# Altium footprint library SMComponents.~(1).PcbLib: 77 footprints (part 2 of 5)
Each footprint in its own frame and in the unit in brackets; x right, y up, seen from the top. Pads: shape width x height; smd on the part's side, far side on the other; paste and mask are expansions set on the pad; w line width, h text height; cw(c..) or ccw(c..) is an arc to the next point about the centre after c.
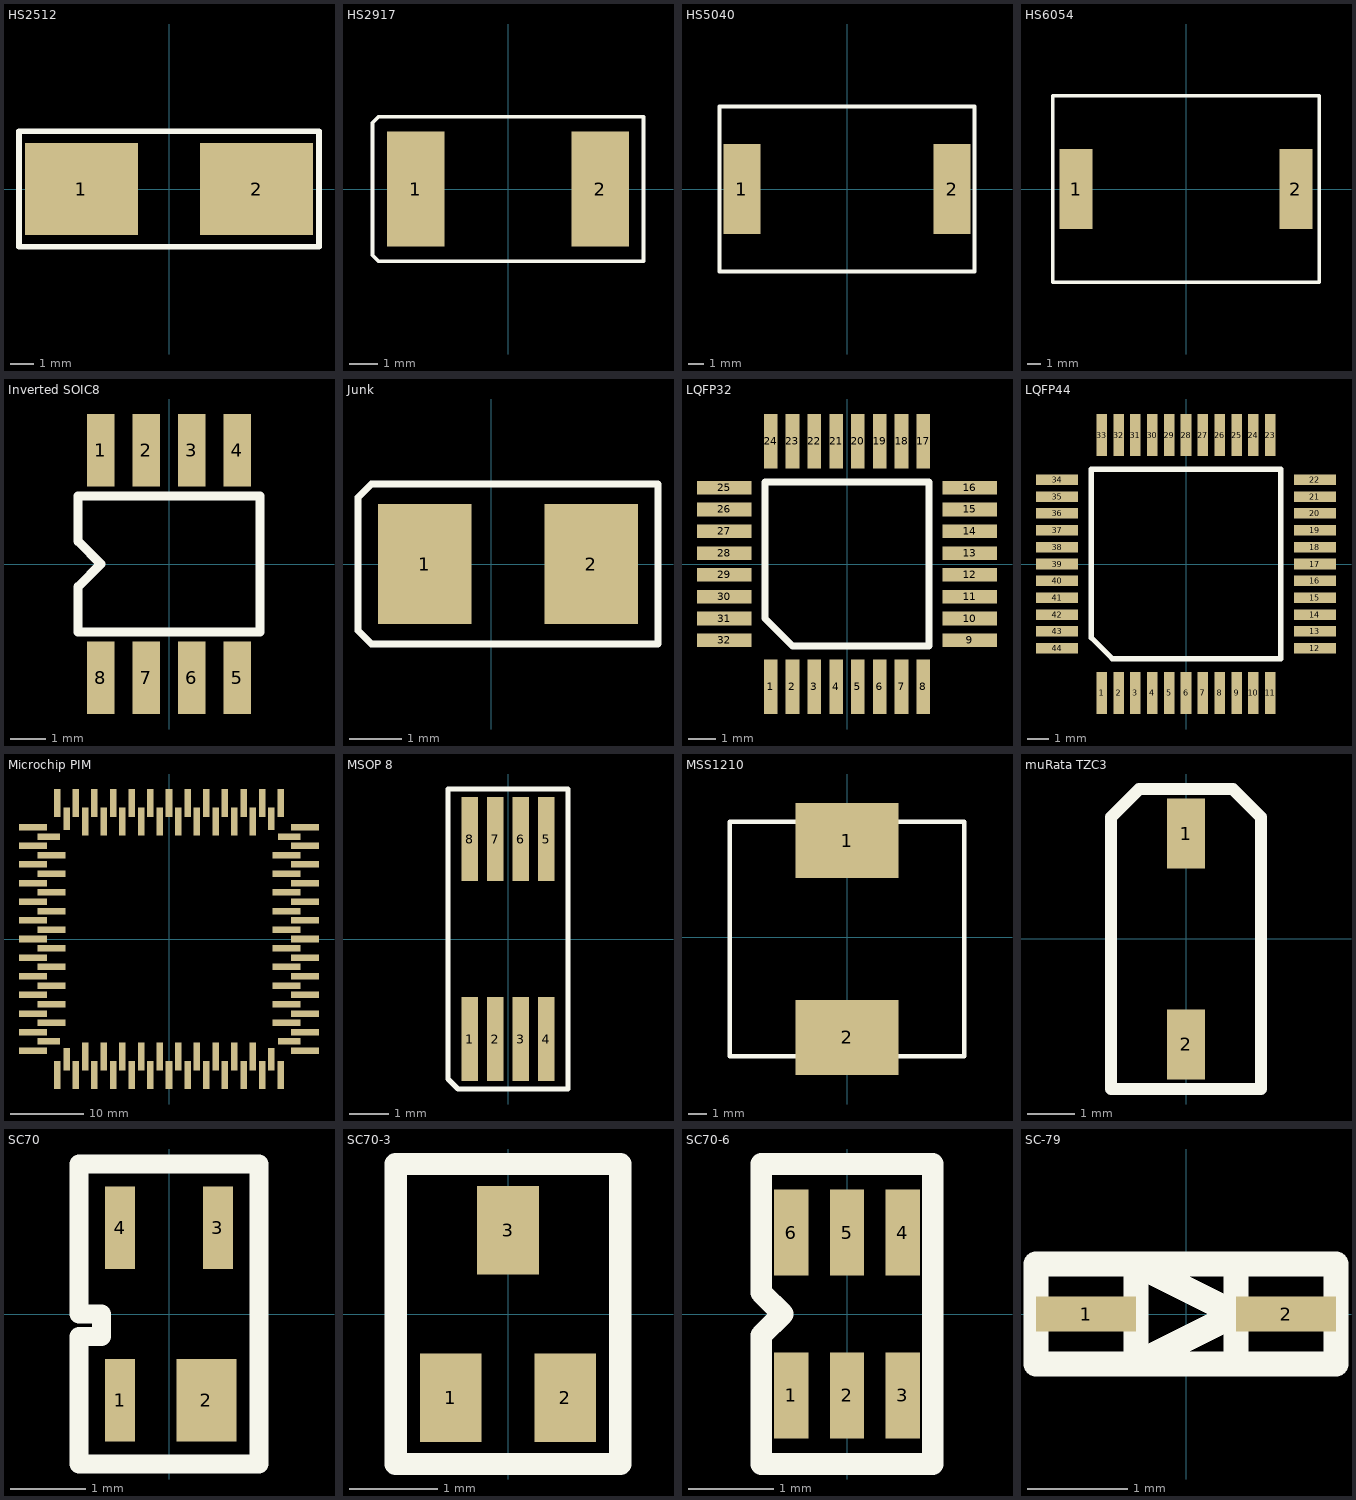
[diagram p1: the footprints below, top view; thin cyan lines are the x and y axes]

## HS2512 [mm] "2512"
height 2.6
pads (2):
  rect 4.9x4 smd: 1(-3.8,0) 2(3.8,0)
Top Overlay:
  lines w0.254: -6.5,-2.5 -6.5,2.5 6.5,2.5 6.5,-2.5 -6.5,-2.5

## HS2917 [mm] "2917 - Tant codes D & E"
height 4.1
pads (2):
  rect 2x4 smd: 1(-3.2,0) 2(3.2,0)
Top Overlay:
  lines w0.127: -4.7,-2.3 -4.7,2.3 -4.5,2.5 4.7,2.5 4.7,-2.5 -4.5,-2.5 -4.7,-2.3

## HS5040 [mm] "5040 SMD such as Wima SMD-PET"
height 6
pads (2):
  rect 2.5x6 smd: 1(-7,0) 2(7,0)
Top Overlay:
  lines w0.254: -8.5,-5.5 -8.5,5.5 8.5,5.5 8.5,-5.5 -8.5,-5.5

## HS6054 [mm] "6054 SMD such as Wima SMD-PET"
height 6
pads (2):
  rect 2.5x6 smd: 1(-8.25,0) 2(8.25,0)
Top Overlay:
  lines w0.254: -10,-7 -10,7 10,7 10,-7 -10,-7

## Inverted SOIC8 [mil] "Inverted to allow access to power pad - cut out in board!"
pads (8):
  rect 30x80 smd: 1(-75,125) 2(-25,125) 3(25,125) 4(75,125) 5(75,-125) 6(25,-125) 7(-25,-125) 8(-75,-125)
Top Overlay:
  lines w10: -100,-75 100,-75 100,75 -100,75 -100,25 -75,0 -100,-25 -100,-75
Bottom Overlay:
  lines w10: -98.43,-78.74 -98.43,78.74 98.43,78.74 98.43,-78.74 -98.43,-78.74

## Junk [mil] "Tant case B (A will also fit!)"
height 74.8
pads (2):
  rect 70x90 smd: 1(-50,0) 2(75,0)
Top Overlay:
  lines w5: -100,-50 -100,50 -90,60 125,60 125,-60 -90,-60 -100,-50

## LQFP32 [mm] "LQFP32"
height 1.6
pads (32):
  rect 0.5x2 smd: 1(-2.8,-4.5) 2(-2,-4.5) 3(-1.2,-4.5) 4(-0.4,-4.5) 5(0.4,-4.5) 6(1.2,-4.5) 7(2,-4.5) 8(2.8,-4.5) 17(2.8,4.5) 18(2,4.5) 19(1.2,4.5) 20(0.4,4.5) 21(-0.4,4.5) 22(-1.2,4.5) 23(-2,4.5) 24(-2.8,4.5)
  rect 2x0.5 smd: 9(4.5,-2.8) 10(4.5,-2) 11(4.5,-1.2) 12(4.5,-0.4) 13(4.5,0.4) 14(4.5,1.2) 15(4.5,2) 16(4.5,2.8) 25(-4.5,2.8) 26(-4.5,2) 27(-4.5,1.2) 28(-4.5,0.4) 29(-4.5,-0.4) 30(-4.5,-1.2) 31(-4.5,-2) 32(-4.5,-2.8)
Top Overlay:
  lines w0.254: -3,-2 -2,-3 3,-3 3,3 -3,3 -3,-2

## LQFP44 [mm] "LQFP44"
height 1.6
pads (44):
  rect 0.5x2 smd: 1(-4,-6.125) 2(-3.2,-6.125) 3(-2.4,-6.125) 4(-1.6,-6.125) 5(-0.8,-6.125) 6(0,-6.125) 7(0.8,-6.125) 8(1.6,-6.125) 9(2.4,-6.125) 10(3.2,-6.125) 11(4,-6.125) 23(4,6.125) 24(3.2,6.125) 25(2.4,6.125) 26(1.6,6.125) 27(0.8,6.125) 28(0,6.125) 29(-0.8,6.125) 30(-1.6,6.125) 31(-2.4,6.125) 32(-3.2,6.125) 33(-4,6.125)
  rect 2x0.5 smd: 12(6.125,-4) 13(6.125,-3.2) 14(6.125,-2.4) 15(6.125,-1.6) 16(6.125,-0.8) 17(6.125,0) 18(6.125,0.8) 19(6.125,1.6) 20(6.125,2.4) 21(6.125,3.2) 22(6.125,4) 34(-6.125,4) 35(-6.125,3.2) 36(-6.125,2.4) 37(-6.125,1.6) 38(-6.125,0.8) 39(-6.125,0) 40(-6.125,-0.8) 41(-6.125,-1.6) 42(-6.125,-2.4) 43(-6.125,-3.2) 44(-6.125,-4)
Top Overlay:
  lines w0.254: -4.5,-3.5 -3.5,-4.5 4.5,-4.5 4.5,4.5 -4.5,4.5 -4.5,-3.5

## Microchip PIM [mil] "High pincount PIC on PCB"
height 787.4
pads (100):
  rect 150x35 smd: 1(-730,600) 3(-730,500) 4(-630,450) 5(-730,400) 6(-630,350) 7(-730,300) 8(-630,250) 9(-730,200) 10(-630,150) 11(-730,100) 12(-630,50) 13(-730,0) 14(-630,-50) 15(-730,-100) 16(-630,-150) 17(-730,-200) 18(-630,-250) 19(-730,-300) 20(-630,-350) 21(-730,-400) 22(-630,-450) 23(-730,-500) 25(-730,-600) 51(730,-600) 53(730,-500) 54(630,-450) 55(730,-400) 56(630,-350) 57(730,-300) 58(630,-250) 59(730,-200) 60(630,-150) 61(730,-100) 62(630,-50) 63(730,0) 64(630,50) 65(730,100) 66(630,150) 67(730,200) 68(630,250) 69(730,300) 70(630,350) 71(730,400) 72(630,450) 73(730,500) 75(730,600)
  rect 120x35 smd: 2(-645,550) 24(-645,-550) 52(645,-550) 74(645,550)
  rect 35x150 smd: 26(-600,-730) 28(-500,-730) 29(-450,-630) 30(-400,-730) 31(-350,-630) 32(-300,-730) 33(-250,-630) 34(-200,-730) 35(-150,-630) 36(-100,-730) 37(-50,-630) 38(0,-730) 39(50,-630) 40(100,-730) 41(150,-630) 42(200,-730) 43(250,-630) 44(300,-730) 45(350,-630) 46(400,-730) 47(450,-630) 48(500,-730) 50(600,-730) 76(600,730) 78(500,730) 79(450,630) 80(400,730) 81(350,630) 82(300,730) 83(250,630) 84(200,730) 85(150,630) 86(100,730) 87(50,630) 88(0,730) 89(-50,630) 90(-100,730) 91(-150,630) 92(-200,730) 93(-250,630) 94(-300,730) 95(-350,630) 96(-400,730) 97(-450,630) 98(-500,730) 100(-600,730)
  rect 35x120 smd: 27(-550,-645) 49(550,-645) 77(550,645) 99(-550,645)
Bottom Overlay:
  lines w10: -800,-800 -800,700 -700,800 800,800 800,-800 -800,-800

## MSOP 8 [mm] "MSOP 8 package (Oversize pads)"
height 2
pads (8):
  rect 0.415x2.13 smd: 1(-0.975,-2.54) 2(-0.325,-2.54) 3(0.325,-2.54) 4(0.975,-2.54) 5(0.975,2.54) 6(0.325,2.54) 7(-0.325,2.54) 8(-0.975,2.54)
Top Overlay:
  lines w0.127: -1.524,-3.556 -1.524,3.81 1.524,3.81 1.524,-3.81 -1.27,-3.81 -1.524,-3.556

## MSS1210 [mm]
height 10
pads (2):
  rect 5.5x4 smd: 1(0,5.166) 2(0,-5.334)
Top Overlay:
  lines w0.254: -6.25,-6.334 -6.25,6.166 6.25,6.166 6.25,-6.334 -6.25,-6.334

## muRata TZC3 [mm] "muRata TZC3 series VCap"
height 1.6
pads (2):
  rect 0.8x1.5 smd: 1(0,2.25) 2(0,-2.25)
Top Overlay:
  lines w0.254: -1.6,-3.2 1.6,-3.2 1.6,2.6 1,3.2 -1,3.2 -1.6,2.6 -1.6,-3.2 ; -1.6,-3.2 -1.6,-3.2

## SC70 [mm] "4 lead thin shink Transisitor"
pads (4):
  rect 0.4x1.1 smd: 1(-0.65,-1.15) 3(0.65,1.15) 4(-0.65,1.15)
  rect 0.8x1.1 smd: 2(0.5,-1.15)
Top Overlay:
  lines w0.254: -1.2,-2 -1.1,-2 1.2,-2 1.2,2 -1.2,2 -1.2,0 -0.9,0 -0.9,-0.3 -1.2,-0.3 -1.2,-2

## SC70-3 [mm] "SC70 3 pad"
height 1
pads (3):
  rect 0.7x1 smd: 1(-0.65,-0.95) 2(0.65,-0.95) 3(0,0.95)
Top Overlay:
  lines w0.254: -1.27,-1.7 1.27,-1.7 1.27,1.7 -1.27,1.7 -1.27,-1.7

## SC70-6 [mm] "SC70 six pin"
height 1.1
pads (6):
  rect 0.4x1 smd: 1(-0.65,-0.95) 2(0,-0.95) 3(0.65,-0.95) 4(0.65,0.95) 5(0,0.95) 6(-0.65,0.95)
Top Overlay:
  lines w0.254: -1,-1.75 1,-1.75 1,1.75 -1,1.75 -1,0.25 -0.75,0 -1,-0.25 -1,-1.5 -1,-1.75

## SC-79 [mm] "SC-79 Diode"
height 0.6
pads (2):
  rect 1x0.35 smd: 1(-1,0) 2(1,0)
Top Overlay:
  lines w0.254: 0.5,-0.5 0.5,0.5 ; -1.5,-0.5 -1.5,0.5 1.5,0.5 1.5,-0.5 -1.5,-0.5 ; -0.5,-0.5 0.5,0 -0.5,0.5 -0.5,-0.5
